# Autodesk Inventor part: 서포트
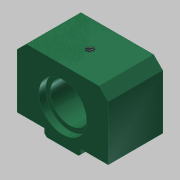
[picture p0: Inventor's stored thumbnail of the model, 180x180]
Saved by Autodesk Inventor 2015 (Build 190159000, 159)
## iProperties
Created: 2019-04
Part Number: 서포트
Material: 알루미늄 6061
Document SubType Name: Modeling
Designer: mduedu
Density: 1 g/cm^3
Appearance: 매끄러움 - 짙은 바다 녹색
Author: mduedu
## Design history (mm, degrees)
sketch "스케치1"
  geometry: L1 (3, 20)-(31, 20); L2 (31, 20)-(31, -20); L3 (31, -20)-(3, -20); L4 (0, -8)-(0, 8); L5 (0, 8)-(3, 8); L6 (3, 8)-(3, 20); L7 (0, 0)-(31, 0); L8 (0, -8)-(3, -8); L9 (3, -8)-(3, -20); 1 further point
  constraints: 18 end point, 3 symmetric about line, 2 horizontal, 2 midpoint, 2 parallel, 2 perpendicular, 1 coincident
  dimensions: "d3" = 31 distance between parallel lines of L4 L2; "d5" = 16 distance of L4.start L4.end; "d6" = 40 distance between parallel lines of L3 L1; "d7" = 3 distance between parallel lines of L4 L9
extrude "돌출1" new body sketch "스케치1" distance "d8" = 24; taper "d9" = 0 deg
chamfer "모따기1" distance "d10" = 4; stored, may be unused: second distance "d11" = 2, angle "d12" = 45 deg
chamfer "모따기2" distance "d13" = 1; stored, may be unused: second distance "d14" = 2, angle "d15" = 45 deg
sketch "스케치2"
  geometry: L1 (7, 0)-(-7, 0) reference; L2 (20, 3)-(8, 3) reference; 3 further points
  constraints: 1 midpoint, 1 vertical alignment
  dimensions: "d24" = 12 distance from line of point (0, 15) L2
hole "구멍1" sketch "스케치2" at (0, 15) diameter "d17" = 17; stored, may be unused: countersink angle "d21" = 90 deg, drill point angle "d23" = 118 deg; dims "d18" = 6, "d19" = 21, "d20" = 3, "d22" = 8
sketch "스케치3"
  geometry: L1 (0, 32)-(0, 0) reference; 3 further points
  constraints: 1 horizontal alignment, 1 midpoint
  dimensions: "d25" = 12 distance from line of point (12, 16) L1
hole "구멍2" sketch "스케치3" at (12, 16) diameter "d26" = 3.242; stored, may be unused: countersink angle "d30" = 90 deg, drill point angle "d32" = 118 deg; dims "d27" = 6, "d28" = 21, "d29" = 3, "d31" = 8
sketch "스케치4"
  geometry: L1 (0, -8)-(24, -8); L2 (24, 0.5)-(24, -16.5) reference; L3 (0, -28)-(0, -24) reference; 4 further points
  constraints: 2 end point, 2 symmetric about line, 1 horizontal, 1 horizontal alignment, 1 midpoint
  dimensions: "d33" = 6 distance from line of point (6, -22) L3; "d34" = 12 distance of point (18, -22) point (6, -22); "d35" = 28 distance of point (6, 6) point (6, -22); "d36" = 14 distance from line of point (6, -22) L1 (derived)
hole "구멍3" sketch "스케치4" at (6, -22), (18, -22), (18, 6), (6, 6) diameter "d37" = 3.242; stored, may be unused: countersink angle "d41" = 90 deg, drill point angle "d43" = 118 deg; dims "d38" = 9, "d39" = 21, "d40" = 3, "d42" = 11
node "솔리드1"
